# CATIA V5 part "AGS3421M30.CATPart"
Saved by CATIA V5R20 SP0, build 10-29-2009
Part number: AGS3421M30
Definition: NONE
Nomenclature: AGS3421M30
Source: Unknown
Description: AGS3421M30
Bounding box of the stored display mesh (mm): x -30 to 50, y -21.312 to 21.312, z -17.2 to 17.2
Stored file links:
  C:\Users\Utente\Desktop\IO LAVORO\3D X SITO CF\X SITO\PLASTICA\AGS\AGS3421M30.CATPart
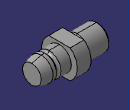
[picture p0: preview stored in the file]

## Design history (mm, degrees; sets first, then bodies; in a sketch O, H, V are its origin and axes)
Body1 "AGS3421M30" (main body)
  Solid1: solid without history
